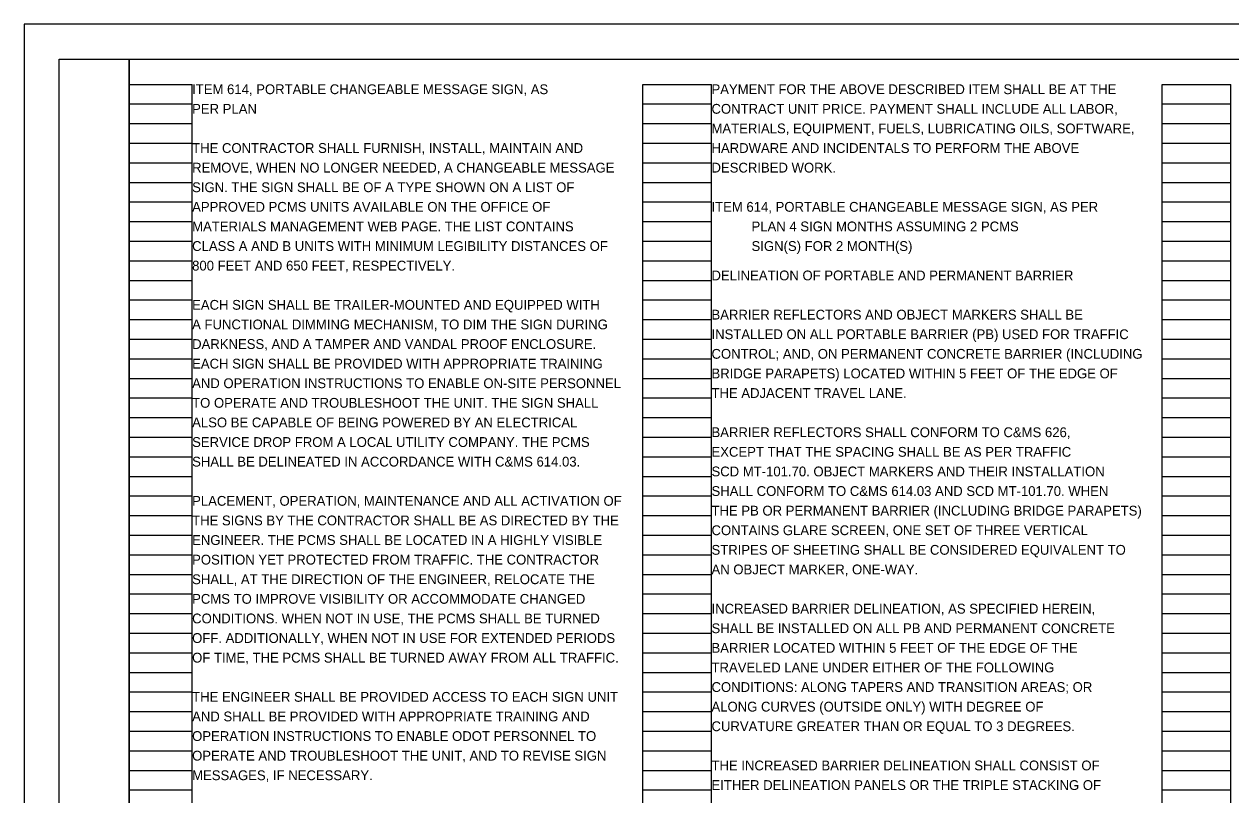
# Model space of a CAD drawing. Extents: x 0 to 50.5, y 0 to 22.
# Drawn here: x 0 to 17.24, y 10.99 to 22 of the extents above; entities that cross this region are included whole.
import ezdxf

# ---------------------------------------------------------------- set-up
doc = ezdxf.new("R2010")
doc.units = 0
for name, color, linetype in [('SH_Border', 7, 'Continuous'), ('SH_Cut_Line', 7, 'Continuous'), ('SH_Data', 7, 'Continuous'), ('SH_Text', 7, 'Continuous')]:
    doc.layers.add(name, color=color, linetype=linetype)

msp = doc.modelspace()

# ---------------------------------------------------------------- linework, layer by layer
at = {"layer": 'SH_Border'}
for points in [[(0.5, 21.5), (1.5, 21.5), (1.5, 0.5), (0.5, 0.5)], [(1.5, 21.5), (33.5, 21.5), (33.5, 0.5), (1.5, 0.5)]]:
    msp.add_lwpolyline(points, close=True, dxfattribs=at)
at = {"layer": 'SH_Cut_Line'}
msp.add_lwpolyline([(0, 0), (34, 0), (34, 22), (0, 22)], close=True, dxfattribs=at)
at = {"layer": 'SH_Data'}
for p, q in [((1.5, 0.98), (1.5, 21.14)), ((1.5, 21.14), (2.4, 21.14)), ((2.4, 0.98), (2.4, 21.14)), ((8.84, 0.98), (8.84, 21.14)), ((8.84, 21.14), (9.82, 21.14)), ((9.82, 0.98), (9.82, 21.14)), ((16.26, 0.98), (16.26, 21.14)), ((16.26, 21.14), (17.24, 21.14)), ((17.24, 0.98), (17.24, 21.14)), ((1.5, 20.86), (2.4, 20.86)), ((8.84, 20.86), (9.82, 20.86)), ((16.26, 20.86), (17.24, 20.86)), ((1.5, 20.58), (2.4, 20.58)), ((8.84, 20.58), (9.82, 20.58)), ((16.26, 20.58), (17.24, 20.58)), ((1.5, 20.3), (2.4, 20.3)), ((8.84, 20.3), (9.82, 20.3)), ((16.26, 20.3), (17.24, 20.3)), ((1.5, 20.02), (2.4, 20.02)), ((8.84, 20.02), (9.82, 20.02)), ((16.26, 20.02), (17.24, 20.02)), ((1.5, 19.74), (2.4, 19.74)), ((8.84, 19.74), (9.82, 19.74)), ((16.26, 19.74), (17.24, 19.74)), ((1.5, 19.46), (2.4, 19.46)), ((8.84, 19.46), (9.82, 19.46)), ((16.26, 19.46), (17.24, 19.46)), ((1.5, 19.18), (2.4, 19.18)), ((8.84, 19.18), (9.82, 19.18)), ((16.26, 19.18), (17.24, 19.18)), ((1.5, 18.9), (2.4, 18.9)), ((8.84, 18.9), (9.82, 18.9)), ((16.26, 18.9), (17.24, 18.9)), ((1.5, 18.62), (2.4, 18.62)), ((8.84, 18.62), (9.82, 18.62)), ((16.26, 18.62), (17.24, 18.62)), ((1.5, 18.34), (2.4, 18.34)), ((8.84, 18.34), (9.82, 18.34)), ((16.26, 18.34), (17.24, 18.34)), ((1.5, 18.06), (2.4, 18.06)), ((8.84, 18.06), (9.82, 18.06)), ((16.26, 18.06), (17.24, 18.06)), ((1.5, 17.78), (2.4, 17.78)), ((8.84, 17.78), (9.82, 17.78)), ((16.26, 17.78), (17.24, 17.78)), ((1.5, 17.5), (2.4, 17.5)), ((8.84, 17.5), (9.82, 17.5)), ((16.26, 17.5), (17.24, 17.5)), ((1.5, 17.22), (2.4, 17.22)), ((8.84, 17.22), (9.82, 17.22)), ((16.26, 17.22), (17.24, 17.22)), ((1.5, 16.94), (2.4, 16.94)), ((8.84, 16.94), (9.82, 16.94)), ((16.26, 16.94), (17.24, 16.94)), ((1.5, 16.66), (2.4, 16.66)), ((8.84, 16.66), (9.82, 16.66)), ((16.26, 16.66), (17.24, 16.66)), ((1.5, 16.38), (2.4, 16.38)), ((8.84, 16.38), (9.82, 16.38)), ((16.26, 16.38), (17.24, 16.38)), ((1.5, 16.1), (2.4, 16.1)), ((8.84, 16.1), (9.82, 16.1)), ((16.26, 16.1), (17.24, 16.1)), ((1.5, 15.82), (2.4, 15.82)), ((8.84, 15.82), (9.82, 15.82)), ((16.26, 15.82), (17.24, 15.82)), ((1.5, 15.54), (2.4, 15.54)), ((8.84, 15.54), (9.82, 15.54)), ((16.26, 15.54), (17.24, 15.54)), ((1.5, 15.26), (2.4, 15.26)), ((8.84, 15.26), (9.82, 15.26)), ((16.26, 15.26), (17.24, 15.26)), ((1.5, 14.98), (2.4, 14.98)), ((8.84, 14.98), (9.82, 14.98)), ((16.26, 14.98), (17.24, 14.98)), ((1.5, 14.7), (2.4, 14.7)), ((8.84, 14.7), (9.82, 14.7)), ((16.26, 14.7), (17.24, 14.7)), ((1.5, 14.42), (2.4, 14.42)), ((8.84, 14.42), (9.82, 14.42)), ((16.26, 14.42), (17.24, 14.42)), ((1.5, 14.14), (2.4, 14.14)), ((8.84, 14.14), (9.82, 14.14)), ((16.26, 14.14), (17.24, 14.14)), ((1.5, 13.86), (2.4, 13.86)), ((8.84, 13.86), (9.82, 13.86)), ((16.26, 13.86), (17.24, 13.86)), ((1.5, 13.58), (2.4, 13.58)), ((8.84, 13.58), (9.82, 13.58)), ((16.26, 13.58), (17.24, 13.58)), ((1.5, 13.3), (2.4, 13.3)), ((8.84, 13.3), (9.82, 13.3)), ((16.26, 13.3), (17.24, 13.3)), ((1.5, 13.02), (2.4, 13.02)), ((8.84, 13.02), (9.82, 13.02)), ((16.26, 13.02), (17.24, 13.02)), ((1.5, 12.74), (2.4, 12.74)), ((8.84, 12.74), (9.82, 12.74)), ((16.26, 12.74), (17.24, 12.74)), ((1.5, 12.46), (2.4, 12.46)), ((8.84, 12.46), (9.82, 12.46)), ((16.26, 12.46), (17.24, 12.46)), ((1.5, 12.18), (2.4, 12.18)), ((8.84, 12.18), (9.82, 12.18)), ((16.26, 12.18), (17.24, 12.18)), ((1.5, 11.9), (2.4, 11.9)), ((8.84, 11.9), (9.82, 11.9)), ((16.26, 11.9), (17.24, 11.9)), ((1.5, 11.62), (2.4, 11.62)), ((8.84, 11.62), (9.82, 11.62)), ((16.26, 11.62), (17.24, 11.62)), ((1.5, 11.34), (2.4, 11.34)), ((8.84, 11.34), (9.82, 11.34)), ((16.26, 11.34), (17.24, 11.34)), ((1.5, 11.06), (2.4, 11.06)), ((8.84, 11.06), (9.82, 11.06)), ((16.26, 11.06), (17.24, 11.06))]:
    msp.add_line(p, q, dxfattribs=at)

# ---------------------------------------------------------------- texts
at = {"layer": 'SH_Text'}
for s, p in [('ITEM 614, PORTABLE CHANGEABLE MESSAGE SIGN, AS', (2.4, 21)), ('PAYMENT FOR THE ABOVE DESCRIBED ITEM SHALL BE AT THE', (9.82, 21)), ('CONTRACT UNIT PRICE. PAYMENT SHALL INCLUDE ALL LABOR,', (9.82, 20.72)), ('PER PLAN', (2.4, 20.72)), ('MATERIALS, EQUIPMENT, FUELS, LUBRICATING OILS, SOFTWARE,', (9.82, 20.44)), ('THE CONTRACTOR SHALL FURNISH, INSTALL, MAINTAIN AND', (2.4, 20.16)), ('HARDWARE AND INCIDENTALS TO PERFORM THE ABOVE', (9.82, 20.16)), ('REMOVE, WHEN NO LONGER NEEDED, A CHANGEABLE MESSAGE', (2.4, 19.88)), ('DESCRIBED WORK.', (9.82, 19.88)), ('SIGN. THE SIGN SHALL BE OF A TYPE SHOWN ON A LIST OF', (2.4, 19.6)), ('APPROVED PCMS UNITS AVAILABLE ON THE OFFICE OF', (2.4, 19.32)), ('ITEM 614, PORTABLE CHANGEABLE MESSAGE SIGN, AS PER', (9.82, 19.32)), ('MATERIALS MANAGEMENT WEB PAGE. THE LIST CONTAINS', (2.4, 19.04)), ('           PLAN 4 SIGN MONTHS ASSUMING 2 PCMS', (9.82, 19.04)), ('CLASS A AND B UNITS WITH MINIMUM LEGIBILITY DISTANCES OF', (2.4, 18.76)), ('           SIGN(S) FOR 2 MONTH(S)', (9.82, 18.76)), ('800 FEET AND 650 FEET, RESPECTIVELY.', (2.4, 18.48)), ('DELINEATION OF PORTABLE AND PERMANENT BARRIER', (9.82, 18.34)), ('EACH SIGN SHALL BE TRAILER-MOUNTED AND EQUIPPED WITH', (2.4, 17.92)), ('A FUNCTIONAL DIMMING MECHANISM, TO DIM THE SIGN DURING', (2.4, 17.64)), ('BARRIER REFLECTORS AND OBJECT MARKERS SHALL BE', (9.82, 17.78)), ('INSTALLED ON ALL PORTABLE BARRIER (PB) USED FOR TRAFFIC', (9.82, 17.5)), ('DARKNESS, AND A TAMPER AND VANDAL PROOF ENCLOSURE.', (2.4, 17.36)), ('CONTROL; AND, ON PERMANENT CONCRETE BARRIER (INCLUDING', (9.82, 17.22)), ('EACH SIGN SHALL BE PROVIDED WITH APPROPRIATE TRAINING', (2.4, 17.08)), ('BRIDGE PARAPETS) LOCATED WITHIN 5 FEET OF THE EDGE OF', (9.82, 16.94)), ('AND OPERATION INSTRUCTIONS TO ENABLE ON-SITE PERSONNEL', (2.4, 16.8)), ('THE ADJACENT TRAVEL LANE.', (9.82, 16.66)), ('TO OPERATE AND TROUBLESHOOT THE UNIT. THE SIGN SHALL', (2.4, 16.52)), ('ALSO BE CAPABLE OF BEING POWERED BY AN ELECTRICAL', (2.4, 16.24)), ('BARRIER REFLECTORS SHALL CONFORM TO C&MS 626,', (9.82, 16.1)), ('SERVICE DROP FROM A LOCAL UTILITY COMPANY. THE PCMS', (2.4, 15.96)), ('EXCEPT THAT THE SPACING SHALL BE AS PER TRAFFIC', (9.82, 15.82)), ('SHALL BE DELINEATED IN ACCORDANCE WITH C&MS 614.03.', (2.4, 15.68)), ('SCD MT-101.70. OBJECT MARKERS AND THEIR INSTALLATION', (9.82, 15.54)), ('SHALL CONFORM TO C&MS 614.03 AND SCD MT-101.70. WHEN', (9.82, 15.26)), ('PLACEMENT, OPERATION, MAINTENANCE AND ALL ACTIVATION OF', (2.4, 15.12)), ('THE PB OR PERMANENT BARRIER (INCLUDING BRIDGE PARAPETS)', (9.82, 14.98)), ('THE SIGNS BY THE CONTRACTOR SHALL BE AS DIRECTED BY THE', (2.4, 14.84)), ('CONTAINS GLARE SCREEN, ONE SET OF THREE VERTICAL', (9.82, 14.7)), ('ENGINEER. THE PCMS SHALL BE LOCATED IN A HIGHLY VISIBLE', (2.4, 14.56)), ('STRIPES OF SHEETING SHALL BE CONSIDERED EQUIVALENT TO', (9.82, 14.42)), ('POSITION YET PROTECTED FROM TRAFFIC. THE CONTRACTOR', (2.4, 14.28)), ('SHALL, AT THE DIRECTION OF THE ENGINEER, RELOCATE THE', (2.4, 14)), ('AN OBJECT MARKER, ONE-WAY.', (9.82, 14.14)), ('PCMS TO IMPROVE VISIBILITY OR ACCOMMODATE CHANGED', (2.4, 13.72)), ('INCREASED BARRIER DELINEATION, AS SPECIFIED HEREIN,', (9.82, 13.58)), ('CONDITIONS. WHEN NOT IN USE, THE PCMS SHALL BE TURNED', (2.4, 13.44)), ('OFF. ADDITIONALLY, WHEN NOT IN USE FOR EXTENDED PERIODS', (2.4, 13.16)), ('SHALL BE INSTALLED ON ALL PB AND PERMANENT CONCRETE', (9.82, 13.3)), ('BARRIER LOCATED WITHIN 5 FEET OF THE EDGE OF THE', (9.82, 13.02)), ('OF TIME, THE PCMS SHALL BE TURNED AWAY FROM ALL TRAFFIC.', (2.4, 12.88)), ('TRAVELED LANE UNDER EITHER OF THE FOLLOWING', (9.82, 12.74)), ('CONDITIONS: ALONG TAPERS AND TRANSITION AREAS; OR', (9.82, 12.46)), ('THE ENGINEER SHALL BE PROVIDED ACCESS TO EACH SIGN UNIT', (2.4, 12.32)), ('ALONG CURVES (OUTSIDE ONLY) WITH DEGREE OF', (9.82, 12.18)), ('AND SHALL BE PROVIDED WITH APPROPRIATE TRAINING AND', (2.4, 12.04)), ('OPERATION INSTRUCTIONS TO ENABLE ODOT PERSONNEL TO', (2.4, 11.76)), ('CURVATURE GREATER THAN OR EQUAL TO 3 DEGREES.', (9.82, 11.9)), ('OPERATE AND TROUBLESHOOT THE UNIT, AND TO REVISE SIGN', (2.4, 11.48)), ('THE INCREASED BARRIER DELINEATION SHALL CONSIST OF', (9.82, 11.34)), ('MESSAGES, IF NECESSARY.', (2.4, 11.2)), ('EITHER DELINEATION PANELS OR THE TRIPLE STACKING OF', (9.82, 11.06))]:
    msp.add_text(s, height=0.14, dxfattribs=at).set_placement(p)

doc.saveas('drawing.dxf')
